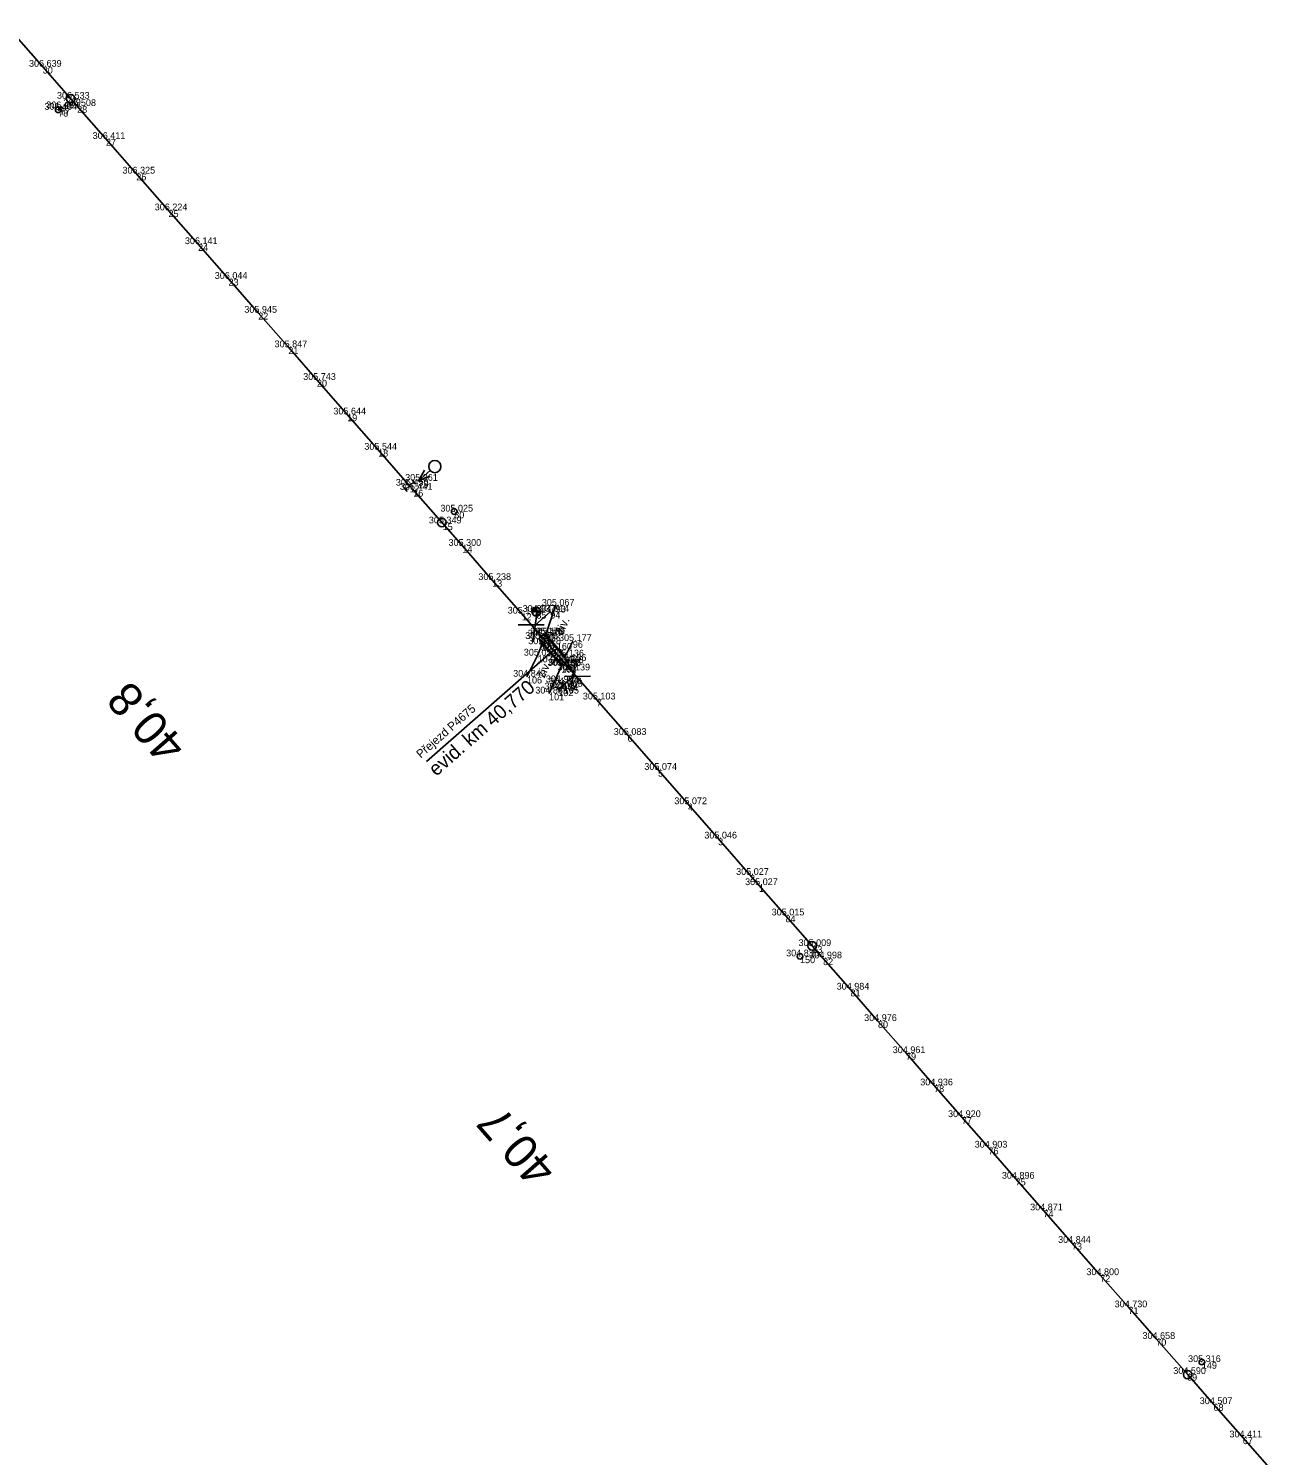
# Model space of a CAD drawing. Extents: x -684938 to -684389, y -1007777 to -1006471.
# Drawn here: x -684817.7 to -684596.3, y -1006797 to -1006543.6 of the extents above; entities that cross this region are included whole.
import ezdxf

# ---------------------------------------------------------------- set-up
doc = ezdxf.new("R2010")
doc.units = 0
for name, color, linetype in [('Vrstva 1', 7, 'Continuous'), ('Vrstva 12', 7, 'Continuous'), ('Vrstva 3', 7, 'Continuous'), ('Vrstva 4', 7, 'Continuous'), ('Vrstva 51', 7, 'Continuous'), ('Vrstva 60', 7, 'Continuous'), ('Vrstva 61', 7, 'Continuous'), ('Vrstva 63', 7, 'Continuous'), ('Vrstva 7', 7, 'Continuous')]:
    doc.layers.add(name, color=color, linetype=linetype)

msp = doc.modelspace()

# ---------------------------------------------------------------- linework, layer by layer
at = {"layer": 'Vrstva 1'}
msp.add_lwpolyline([(-684596.33, -1006800.2), (-684601.97, -1006793.78), (-684607.16, -1006787.87), (-684611.86, -1006782.52), (-684617.33, -1006776.3), (-684622.28, -1006770.68), (-684627.29, -1006764.97), (-684632.32, -1006759.24), (-684637.38, -1006753.46), (-684642.31, -1006747.84), (-684647.14, -1006742.32), (-684651.87, -1006736.9), (-684656.8, -1006731.26), (-684661.79, -1006725.54), (-684666.77, -1006719.84), (-684671.66, -1006714.26), (-684676.52, -1006708.71), (-684678.43, -1006706.52), (-684683.2, -1006701.08), (-684687.93, -1006695.7), (-684689.52, -1006693.88), (-684695.17, -1006687.42), (-684700.5, -1006681.33), (-684705.83, -1006675.23), (-684711.26, -1006669.03), (-684716.76, -1006662.73), (-684721.27, -1006657.57), (-684722.42, -1006656.26), (-684724.49, -1006653.89), (-684726.54, -1006651.55), (-684730.09, -1006647.48), (-684735.31, -1006641.52), (-684740.61, -1006635.45), (-684744.1, -1006631.46), (-684749.34, -1006625.49), (-684749.98, -1006624.76), (-684755.57, -1006618.38), (-684761.07, -1006612.11), (-684766.44, -1006605.97), (-684771.52, -1006600.18), (-684776.88, -1006594.05), (-684782.15, -1006588.03), (-684787.55, -1006581.86), (-684792.81, -1006575.86), (-684798.53, -1006569.33), (-684803.93, -1006563.18), (-684809.04, -1006557.34), (-684810.18, -1006556.04), (-684815.15, -1006550.36), (-684821.1, -1006543.57)], dxfattribs=at)
at = {"layer": 'Vrstva 12'}
msp.add_lwpolyline([(-684723.34, -1006659.67), (-684722.75, -1006660.05), (-684722.58, -1006660.48)], dxfattribs=at)
at = {"layer": 'Vrstva 3'}
for p, q in [((-684750.73, -1006625.42), (-684749.22, -1006624.1)), ((-684748.89, -1006624.48), (-684749.55, -1006623.72)), ((-684748.41, -1006623.9), (-684746.33, -1006622.08)), ((-684750.4, -1006625.79), (-684751.06, -1006625.04))]:
    msp.add_line(p, q, dxfattribs=at)
msp.add_lwpolyline([(-684747.31, -1006622.02), (-684748.41, -1006623.9), (-684746.4, -1006623.06)], dxfattribs=at)
msp.add_circle((-684745.51, -1006621.37), 1.08, dxfattribs=at)
at = {"layer": 'Vrstva 4'}
for p, q in [((-684724.98, -1006647.16), (-684727.63, -1006649.47)), ((-684724.66, -1006647.53), (-684725.31, -1006646.78)), ((-684726.1, -1006649.46), (-684730.71, -1006649.5)), ((-684728.08, -1006652.51), (-684727.41, -1006647.95)), ((-684747, -1006673.72), (-684724.43, -1006653.95)), ((-684720.48, -1006655.59), (-684721.14, -1006660.15)), ((-684723.57, -1006660.94), (-684720.92, -1006658.63)), ((-684722.46, -1006658.64), (-684717.85, -1006658.6)), ((-684723.9, -1006660.57), (-684723.24, -1006661.32))]:
    msp.add_line(p, q, dxfattribs=at)
msp.add_lwpolyline([(-684722.88, -1006656.69), (-684727, -1006651.97), (-684726.06, -1006651.16), (-684721.93, -1006655.87), (-684722.88, -1006656.69)], dxfattribs=at)
at = {"layer": 'Vrstva 51'}
for points in [[(-684724.04, -1006646.08), (-684725.76, -1006651.2), (-684722.34, -1006655.1), (-684720.98, -1006652.35)], [(-684729.13, -1006658.69), (-684727.24, -1006654.94), (-684726.45, -1006652.91), (-684723.02, -1006656.76), (-684725.2, -1006661.67)]]:
    msp.add_lwpolyline(points, dxfattribs=at)
at = {"layer": 'Vrstva 60'}
for p, q in [((-684815.15, -1006550.36), (-684815.15, -1006550.36)), ((-684810.18, -1006556.04), (-684810.18, -1006556.04)), ((-684812.41, -1006558), (-684812.41, -1006558)), ((-684812.08, -1006557.73), (-684812.08, -1006557.73)), ((-684809.04, -1006557.34), (-684809.04, -1006557.34)), ((-684803.93, -1006563.18), (-684803.93, -1006563.18)), ((-684798.53, -1006569.33), (-684798.53, -1006569.33)), ((-684792.81, -1006575.86), (-684792.81, -1006575.86)), ((-684787.55, -1006581.86), (-684787.55, -1006581.86)), ((-684782.15, -1006588.03), (-684782.15, -1006588.03)), ((-684776.88, -1006594.05), (-684776.88, -1006594.05)), ((-684771.52, -1006600.18), (-684771.52, -1006600.18)), ((-684766.44, -1006605.97), (-684766.44, -1006605.97)), ((-684761.07, -1006612.11), (-684761.07, -1006612.11)), ((-684755.57, -1006618.38), (-684755.57, -1006618.38)), ((-684748.41, -1006623.9), (-684748.41, -1006623.9)), ((-684749.98, -1006624.76), (-684749.98, -1006624.76)), ((-684749.34, -1006625.49), (-684749.34, -1006625.49)), ((-684742.05, -1006629.36), (-684742.05, -1006629.36)), ((-684744.1, -1006631.46), (-684744.1, -1006631.46)), ((-684740.61, -1006635.45), (-684740.61, -1006635.45)), ((-684735.31, -1006641.52), (-684735.31, -1006641.52)), ((-684727.46, -1006647.17), (-684727.46, -1006647.17)), ((-684724.98, -1006647.16), (-684724.98, -1006647.16)), ((-684724.04, -1006646.08), (-684724.04, -1006646.08)), ((-684730.09, -1006647.48), (-684730.09, -1006647.48)), ((-684727, -1006651.97), (-684727, -1006651.97)), ((-684726.54, -1006651.55), (-684726.54, -1006651.55)), ((-684726.06, -1006651.16), (-684726.06, -1006651.16)), ((-684725.76, -1006651.2), (-684725.76, -1006651.2)), ((-684720.98, -1006652.35), (-684720.98, -1006652.35)), ((-684727.24, -1006654.94), (-684727.24, -1006654.94)), ((-684726.45, -1006652.91), (-684726.45, -1006652.91)), ((-684724.49, -1006653.89), (-684724.49, -1006653.89)), ((-684723.02, -1006656.76), (-684723.02, -1006656.76)), ((-684722.88, -1006656.69), (-684722.88, -1006656.69)), ((-684722.42, -1006656.26), (-684722.42, -1006656.26)), ((-684722.34, -1006655.1), (-684722.34, -1006655.1)), ((-684721.93, -1006655.87), (-684721.93, -1006655.87)), ((-684729.13, -1006658.69), (-684729.13, -1006658.69)), ((-684723.34, -1006659.67), (-684723.34, -1006659.67)), ((-684721.27, -1006657.57), (-684721.27, -1006657.57)), ((-684725.2, -1006661.67), (-684725.2, -1006661.67)), ((-684723.57, -1006660.94), (-684723.57, -1006660.94)), ((-684722.75, -1006660.05), (-684722.75, -1006660.05)), ((-684722.58, -1006660.48), (-684722.58, -1006660.48)), ((-684716.76, -1006662.73), (-684716.76, -1006662.73)), ((-684711.26, -1006669.03), (-684711.26, -1006669.03)), ((-684705.83, -1006675.23), (-684705.83, -1006675.23)), ((-684700.5, -1006681.33), (-684700.5, -1006681.33)), ((-684695.17, -1006687.42), (-684695.17, -1006687.42)), ((-684689.52, -1006693.88), (-684689.52, -1006693.88)), ((-684687.93, -1006695.7), (-684687.93, -1006695.7)), ((-684683.2, -1006701.08), (-684683.2, -1006701.08)), ((-684678.43, -1006706.52), (-684678.43, -1006706.52)), ((-684680.62, -1006708.35), (-684680.62, -1006708.35)), ((-684676.52, -1006708.71), (-684676.52, -1006708.71)), ((-684671.66, -1006714.26), (-684671.66, -1006714.26)), ((-684666.77, -1006719.84), (-684666.77, -1006719.84)), ((-684661.79, -1006725.54), (-684661.79, -1006725.54)), ((-684656.8, -1006731.26), (-684656.8, -1006731.26)), ((-684651.87, -1006736.9), (-684651.87, -1006736.9)), ((-684647.14, -1006742.32), (-684647.14, -1006742.32)), ((-684642.31, -1006747.84), (-684642.31, -1006747.84)), ((-684637.38, -1006753.46), (-684637.38, -1006753.46)), ((-684632.32, -1006759.24), (-684632.32, -1006759.24)), ((-684627.29, -1006764.97), (-684627.29, -1006764.97)), ((-684622.28, -1006770.68), (-684622.28, -1006770.68)), ((-684617.33, -1006776.3), (-684617.33, -1006776.3)), ((-684609.23, -1006780.4), (-684609.23, -1006780.4)), ((-684611.86, -1006782.52), (-684611.86, -1006782.52)), ((-684607.16, -1006787.87), (-684607.16, -1006787.87)), ((-684601.97, -1006793.78), (-684601.97, -1006793.78))]:
    msp.add_line(p, q, dxfattribs=at)
at = {"layer": 'Vrstva 63'}
for p, q in [((-684727.46, -1006647.17), (-684728.22, -1006647.12)), ((-684727.44, -1006646.96), (-684728.18, -1006646.91)), ((-684727.42, -1006646.66), (-684727.99, -1006646.62)), ((-684727.51, -1006647.93), (-684727.46, -1006647.17)), ((-684727.41, -1006646.4), (-684727.46, -1006647.17)), ((-684727.46, -1006647.17), (-684726.69, -1006647.22)), ((-684726.91, -1006647.7), (-684727.49, -1006647.66)), ((-684726.73, -1006647.41), (-684727.47, -1006647.36))]:
    msp.add_line(p, q, dxfattribs=at)
msp.add_circle((-684727.46, -1006647.17), 0.764, dxfattribs=at)
for start, end in [(86.1893, 176.0828), (265.7385, 356.0566)]:
    msp.add_arc((-684727.46, -1006647.17), 0.765, start, end, dxfattribs=at)
at = {"layer": 'Vrstva 7'}
for p, q in [((-684812.46, -1006558.05), (-684811.71, -1006557.4)), ((-684812.38, -1006558.03), (-684812.44, -1006557.96)), ((-684811.76, -1006558.1), (-684812.41, -1006557.35)), ((-684742.02, -1006629.4), (-684742.09, -1006629.32)), ((-684680.59, -1006708.39), (-684680.65, -1006708.32)), ((-684609.2, -1006780.44), (-684609.26, -1006780.36))]:
    msp.add_line(p, q, dxfattribs=at)
for centre, radius in [((-684810.18, -1006556.04), 0.75), ((-684812.41, -1006558), 0.5), ((-684742.05, -1006629.36), 0.5), ((-684744.26, -1006631.29), 0.75), ((-684680.62, -1006708.35), 0.5), ((-684678.47, -1006706.48), 0.75), ((-684609.23, -1006780.4), 0.5), ((-684611.76, -1006782.63), 0.75)]:
    msp.add_circle(centre, radius, dxfattribs=at)

# ---------------------------------------------------------------- texts
at = {"layer": 'Vrstva 4'}
for s, height, p in [('evid. km 40,770', 2.5, (-684745.25, -1006676.48)), ('Přejezd P4675', 1.5, (-684747.99, -1006673.25))]:
    msp.add_text(s, height=height, rotation=41.2098, dxfattribs=at).set_placement(p)
at = {"layer": 'Vrstva 51'}
for rotation, p in [(65.4587, (-684722.76, -1006651.28)), (66.0809, (-684726.04, -1006659.03))]:
    msp.add_text('živ.', height=1.5, rotation=rotation, dxfattribs=at).set_placement(p)
at = {"layer": 'Vrstva 60'}
for s, p in [('30', (-684815.15, -1006551.56)), ('29', (-684810.18, -1006557.24)), ('78', (-684812.41, -1006559.2)), ('77', (-684812.08, -1006558.93)), ('28', (-684809.04, -1006558.54)), ('27', (-684803.93, -1006564.38)), ('26', (-684798.53, -1006570.53)), ('25', (-684792.81, -1006577.06)), ('24', (-684787.55, -1006583.06)), ('23', (-684782.15, -1006589.23)), ('22', (-684776.88, -1006595.25)), ('21', (-684771.52, -1006601.38)), ('20', (-684766.44, -1006607.17)), ('19', (-684761.07, -1006613.31)), ('18', (-684755.57, -1006619.58)), ('79', (-684748.41, -1006625.1)), ('17', (-684749.98, -1006625.96)), ('16', (-684749.34, -1006626.69)), ('80', (-684742.05, -1006630.56)), ('15', (-684744.1, -1006632.66)), ('14', (-684740.61, -1006636.65)), ('13', (-684735.31, -1006642.71)), ('85', (-684727.46, -1006648.37)), ('94', (-684724.98, -1006648.36)), ('93', (-684724.04, -1006647.28)), ('12', (-684730.09, -1006648.68)), ('90', (-684727, -1006653.17)), ('11', (-684726.54, -1006652.75)), ('91', (-684726.06, -1006652.36)), ('92', (-684725.76, -1006652.4)), ('96', (-684720.98, -1006653.55)), ('107', (-684727.24, -1006656.14)), ('108', (-684726.45, -1006654.11)), ('10', (-684724.49, -1006655.09)), ('100', (-684723.02, -1006657.96)), ('99', (-684722.88, -1006657.89)), ('9', (-684722.42, -1006657.46)), ('97', (-684722.34, -1006656.3)), ('98', (-684721.93, -1006657.07)), ('106', (-684729.13, -1006659.89)), ('103', (-684723.34, -1006660.87)), ('8', (-684721.27, -1006658.77)), ('101', (-684725.2, -1006662.87)), ('102', (-684723.57, -1006662.14)), ('104', (-684722.75, -1006661.25)), ('105', (-684722.58, -1006661.68)), ('7', (-684716.76, -1006663.93)), ('6', (-684711.26, -1006670.23)), ('5', (-684705.83, -1006676.44)), ('4', (-684700.5, -1006682.53)), ('3', (-684695.17, -1006688.62)), ('2', (-684689.52, -1006695.08)), ('1', (-684687.93, -1006696.9)), ('84', (-684683.2, -1006702.28)), ('83', (-684678.43, -1006707.72)), ('150', (-684680.62, -1006709.56)), ('82', (-684676.52, -1006709.91)), ('81', (-684671.66, -1006715.46)), ('80', (-684666.77, -1006721.04)), ('79', (-684661.79, -1006726.74)), ('78', (-684656.8, -1006732.46)), ('77', (-684651.87, -1006738.1)), ('76', (-684647.14, -1006743.52)), ('75', (-684642.31, -1006749.04)), ('74', (-684637.38, -1006754.66)), ('73', (-684632.32, -1006760.44)), ('72', (-684627.29, -1006766.17)), ('71', (-684622.28, -1006771.88)), ('70', (-684617.33, -1006777.5)), ('149', (-684609.23, -1006781.6)), ('69', (-684611.86, -1006783.72)), ('68', (-684607.16, -1006789.07)), ('67', (-684601.97, -1006794.98))]:
    msp.add_text(s, height=1.2, dxfattribs=at).set_placement(p)
at = {"layer": 'Vrstva 61'}
for s, p in [('306.639', (-684817.6, -1006550.36)), ('306.533', (-684812.63, -1006556.04)), ('306.464', (-684814.86, -1006558)), ('306.489', (-684814.54, -1006557.73)), ('306.508', (-684811.5, -1006557.34)), ('306.411', (-684806.29, -1006563.18)), ('306.325', (-684800.99, -1006569.33)), ('306.224', (-684795.26, -1006575.86)), ('306.141', (-684789.9, -1006581.86)), ('306.044', (-684784.6, -1006588.03)), ('305.945', (-684779.34, -1006594.05)), ('305.847', (-684773.97, -1006600.18)), ('305.743', (-684768.89, -1006605.97)), ('305.644', (-684763.52, -1006612.11)), ('305.544', (-684758.02, -1006618.38)), ('305.450', (-684752.43, -1006624.76)), ('305.441', (-684751.7, -1006625.49)), ('305.361', (-684750.77, -1006623.9)), ('305.025', (-684744.51, -1006629.36)), ('305.349', (-684746.56, -1006631.46)), ('305.300', (-684743.07, -1006635.45)), ('305.238', (-684737.76, -1006641.52)), ('305.198', (-684732.55, -1006647.48)), ('304.937', (-684729.91, -1006647.17)), ('304.914', (-684727.44, -1006647.16)), ('305.067', (-684726.49, -1006646.08)), ('305.176', (-684729.45, -1006651.97)), ('305.170', (-684728.99, -1006651.55)), ('305.128', (-684728.9, -1006652.91)), ('305.178', (-684728.51, -1006651.16)), ('305.163', (-684728.22, -1006651.2)), ('305.177', (-684723.44, -1006652.35)), ('305.054', (-684729.69, -1006654.94)), ('305.160', (-684726.94, -1006653.89)), ('305.136', (-684724.8, -1006655.1)), ('305.156', (-684724.38, -1006655.87)), ('304.843', (-684731.58, -1006658.69)), ('305.132', (-684725.47, -1006656.76)), ('305.153', (-684725.33, -1006656.69)), ('305.148', (-684724.87, -1006656.26)), ('305.139', (-684723.72, -1006657.57)), ('304.697', (-684726.02, -1006660.94)), ('304.963', (-684725.79, -1006659.67)), ('304.878', (-684725.21, -1006660.05)), ('304.765', (-684725.04, -1006660.48)), ('304.885', (-684727.65, -1006661.67)), ('305.103', (-684719.21, -1006662.73)), ('305.083', (-684713.71, -1006669.03)), ('305.074', (-684708.28, -1006675.23)), ('305.072', (-684702.95, -1006681.33)), ('305.046', (-684697.62, -1006687.42)), ('305.027', (-684691.97, -1006693.88)), ('305.027', (-684690.38, -1006695.7)), ('305.015', (-684685.66, -1006701.08)), ('305.009', (-684680.89, -1006706.52)), ('304.835', (-684683.08, -1006708.35)), ('304.998', (-684678.97, -1006708.71)), ('304.984', (-684674.11, -1006714.26)), ('304.976', (-684669.23, -1006719.84)), ('304.961', (-684664.15, -1006725.54)), ('304.936', (-684659.26, -1006731.26)), ('304.920', (-684654.32, -1006736.9)), ('304.903', (-684649.59, -1006742.32)), ('304.896', (-684644.76, -1006747.84)), ('304.871', (-684639.74, -1006753.46)), ('304.844', (-684634.77, -1006759.24)), ('304.800', (-684629.74, -1006764.97)), ('304.730', (-684624.73, -1006770.68)), ('304.658', (-684619.78, -1006776.3)), ('304.590', (-684614.31, -1006782.52)), ('305.316', (-684611.68, -1006780.4)), ('304.507', (-684609.61, -1006787.87)), ('304.411', (-684604.33, -1006793.78))]:
    msp.add_text(s, height=1.2, dxfattribs=at).set_placement(p)
at = {"layer": 'Vrstva 7'}
for s, rotation, p in [('40,8', 131.2287, (-684789.38, -1006670.83)), ('40,7', 131.2396, (-684723.59, -1006746.03))]:
    msp.add_text(s, height=6, rotation=rotation, dxfattribs=at).set_placement(p)

doc.saveas('drawing.dxf')
